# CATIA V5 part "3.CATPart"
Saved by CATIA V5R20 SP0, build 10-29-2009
Part number: 3
Material "Gold": density 19320 kg/m3, Young's modulus 7.8e+10 Pa, Poisson ratio 0.42, thermal expansion 1.42e-05 1/K
Bounding box of the stored display mesh (mm): x -114.992 to 34.992, y -254.99 to 99.888, z -75 to 75
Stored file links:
  E:\Ehsan\Amoozesh\CATIA\CATIA Course\Advanced\Videos\Session-25\3.CATPart
  D:\CATIA V5R20\B20\intel_a\startup\materials\Catalog.CATMaterial
  D:\CATIA V5R20\B20\intel_a\resources\graphic\figures\CATIA_EnvironmentMap_Loft_512x512.jpg
  D:\CATIA V5R20\B20\intel_a\resources\graphic\figures\CATIA_EnvironmentMap_DSYellow_512x512.jpg
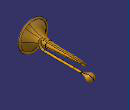
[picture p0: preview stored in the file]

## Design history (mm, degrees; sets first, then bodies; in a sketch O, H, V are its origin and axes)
Set1, material "Gold"
  Sketch1 on yz-plane, origin (0, 0, 0), H (0, 1, 0), V (0, 0, 1)
    line L1 (0, 0) -> (-150, 0)
    arc A1 centre (-150, 25) radius 25 from (-150, 0) to (-150, 50) cw
    line L2 (-150, 50) -> (0, 50)
    point P4 (0, 50)
    line L3 (0, 0) -> (40, 0)
    length L1 = 150
    radius A1 = 25
    length L3 = 40
    horizontal: L1 H
    tangency: A1 L1, L2 A1, L3 A1
    coincidence: P4 V
  Point1: (-40, 0, 0)
  Line1: type PtPt, FirstPoint Sketch1.P4, SecondPoint Point1
  Plane1: type 2Lines, Element1 Line1, Element2 Sketch1.L2
  Sketch2 on Plane1, origin (-24.3902, 0, 19.5122), H (0, -1, 0), V (0.6247, 0, 0.7809)
    point P2 (0, -24.9878)
    arc A1 centre (0, 7.0278) radius 32.0156 from (0, 39.0434) to (0, -24.9878) ccw
  Join1: Elements (Sketch1; Sketch2)
  Line2: type PtDir, RefPoint Sketch2.P2, Direction (0, 1, 0), Start -250, End 0
  Circle1: type CenterAxis, Start 0, End 180, Radius 70, Pt vertex of Line2, Axis Line2
  Sweep1: type Circle, Guide Join1, Radius 5
  Extract1: ExtractElem edge of Sweep1
  Sketch3 on xy-plane, origin (0, 0, 0), H (1, 0, 0), V (0, 1, 0)
    point P1 (-45, 0)
    point P3 (-110, -250)
    spline S1 through (-45, 0) (-47.057, -44.2247) (-53.5254, -134.0406) (-68.0392, -208.7805) (-110, -250)
    point P5 (-45, 0)
    point P6 (-110, -250)
    coincidence: P5 P1, P6 P3
  Sketch4 on xy-plane, origin (0, 0, 0), H (1, 0, 0), V (0, 1, 0)
    frozenspline C1
  Loft1: Sections (Circle1; Extract1), Guides (Sketch3; Sketch4)
  Join2: Elements (Sweep1; Loft1)
  Sketch5 on xy-plane, origin (0, 0, 0), H (1, 0, 0), V (0, 1, 0)
    circle A1 centre (-110, -250) radius 5
    point P1 (-110, -250)
    circle A2 centre (-45, 0) radius 1
    point P2 (-45, 0)
    reference projected point E1 (-40, 0) from vertex of Line2
    circle A3 centre (-56.7547, -169.5884) radius 1
    point P3 (-56.7547, -169.5884)
    reference projected curve E2 from Sketch3.S1
    reference projected line E3 (-90, -250) -> (10, -250) from Circle1
    reference projected point E4 (-110, -250) from Sketch3.P6
    distance E1 P2 H = 5
    radius A3 = 1
    coincidence: P2 H, P3 E2, E3 P1
    concentricity: A1 E4
  Revol1: Element1 Sketch5, Angle1 360, Line Line2
  ThickSurface1: Surface Join2, TopOffset 1, BotOffset 0
  Add1: tool ThickSurface1
  Sketch6 on yz-plane, origin (0, 0, 0), H (0, 1, 0), V (0, 0, 1)
    reference projected line E1 (40, 5) -> (40, -5) from edge [face of ThickSurface1 | face of ThickSurface1]
    point P1 (40, 5)
    spline S1 through (40, 5) (55.7399, 6.6727) (66.9068, 12.0637) (76.1259, 17.0787) (87.0331, 18.2071) (96.2523, 11.6876) (99.888, 0)
    construction line L1 (40, 0) -> (110.4056, 0)
    point P3 (40, 0)
    point P5 (40, 5)
    point P6 (99.888, 0)
    coincidence: P5 P1, P6 L1
    midpoint: P3 E1
    horizontal: L1 H
  Revol2: Element1 Sketch6, Angle1 360, Line Sketch1.L3
  ThickSurface2: Surface Revol2, TopOffset 1, BotOffset 0
Body1 (main body)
